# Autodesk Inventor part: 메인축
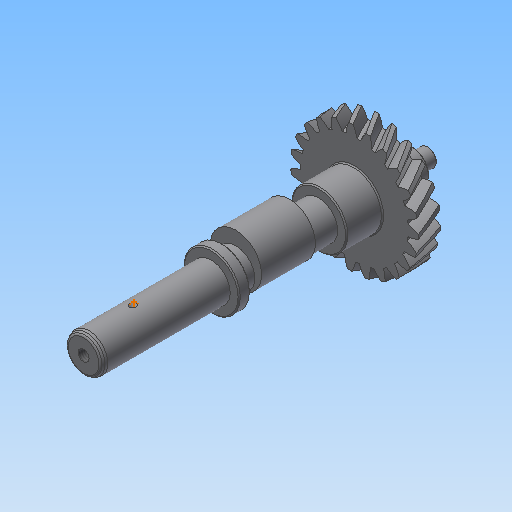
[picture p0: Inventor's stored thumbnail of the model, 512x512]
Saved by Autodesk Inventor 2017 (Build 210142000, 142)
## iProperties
Created: 2016-12
Part Number: 메인축
Material: 강철, 탄소
Document SubType Name: Modeling
Designer: mduedu
Categories: <?xml version="1.0" encoding="UTF-16"?> <MemberInstance><Categories><FamilyTemplate><FamilyTemplateParameter ValueType="xs:double" Id="1" ObjectReferenceKey="da
Density: 7.87 g/cm^3
Appearance: 기본값
Mass: 488.962 g
Surface Area: 171.638 cm^2
Volume: 62.1298 cm^3
CustomPartVersion: 1
Author: mduedu
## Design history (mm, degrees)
sketch "Sketch1"
  geometry: C1 r 28.558 at (0, 0)
  constraints: 1 centre point
  dimensions: "d0" = 57.11622 diameter of C1 (= da_da)
extrude "Extrusion1" new body sketch "Sketch1" distance "d1" = 10 (= da_b); taper "d2" = 0 deg
workplane "Work Plane2"
sketch "Sketch2"
  geometry: C1 r 28.558 at (0, 0) reference; C2 r 26.558 at (0, 0)
  constraints: 1 centre point, 1 coincident
  dimensions: "d3" = 53.11622 diameter of C2 (= da_dw)
feature "피치 지름" sketch "Sketch2" dims "d4" = 10, "d5" = 0
workplane "Work Plane8"
workplane "Work Plane9"
feature "스퍼 기어" dims "da_b" = 10, "da_d" = 53.11622, "da_aw" = 43.87862, "da_da" = 57.11622, "da_df" = 48.11622, "da_dw" = 53.11622, angle "da_beta" = 30 deg, "da_lefttooth" = 10, "da_righttooth" = 0
sketch "스케치3"
  geometry: C1 r 12.5 at (0, 0); 1 further point
  constraints: 1 centre point, 1 coincident
  dimensions: "d49" = 25 diameter of C1
extrude "돌출2" join sketch "스케치3" distance "d50" = 16; taper "d51" = 0 deg
sketch "스케치4"
  geometry: C1 r 8.5 at (0, 0); 1 further point
  constraints: 1 centre point, 1 coincident
  dimensions: "d52" = 17 diameter of C1
extrude "돌출3" join sketch "스케치4" distance "d53" = 105; taper "d54" = 0 deg
sketch "스케치5"
  geometry: C1 r 7.5 at (0, 0); 1 further point
  constraints: 1 centre point, 1 coincident
  dimensions: "d55" = 15 diameter of C1
extrude "돌출4" join sketch "스케치5" distance "d56" = 16; taper "d57" = 0 deg
sketch "스케치6"
  geometry: C1 r 4 at (0, 0); 1 further point
  constraints: 1 centre point, 1 coincident
  dimensions: "d58" = 8 diameter of C1
extrude "돌출5" join sketch "스케치6" distance "d59" = 7; taper "d60" = 0 deg
chamfer "모따기1" distance "d61" = 0.5; stored, may be unused: second distance "d62" = 2, angle "d63" = 45 deg
fillet "모깎기1" dims "d64" = 0.5
node "작업 평면11"
sketch "스케치7"
  geometry: C1 r 11.5 at (0, 3); C2 r 8.5 at (0, 0) reference; 1 further point
  constraints: 1 centre point, 1 tangent, 1 vertical alignment
  dimensions: "d66" = 3 distance of point (0, 0) C1.centre; "d67" = 23 diameter of C1 (derived)
extrude "돌출6" join sketch "스케치7" stored distance "d68" = 24; taper "d69" = 0 deg
node "작업 평면12"
sketch "스케치8"
  geometry: C1 r 12.5 at (0, 0) reference; 1 further point
extrude "돌출7" join sketch "스케치8" distance "d71" = 5; taper "d72" = 0 deg
chamfer "모따기2" distance "d73" = 0.5; stored, may be unused: second distance "d74" = 2, angle "d75" = 45 deg
node "작업 평면13"
sketch "스케치9" dims "d81" = 18
  geometry: L1 (2.5, 95.5)-(-2.5, 95.5); L2 (-2.5, 95.5)-(-2.5, 82.5); L3 (-2.5, 82.5)-(2.5, 82.5); L4 (2.5, 82.5)-(2.5, 95.5); L5 (8.5, 105)-(-8.5, 105) reference; 3 further points
  constraints: 8 end point, 2 horizontal alignment, 2 midpoint, 2 parallel, 1 horizontal, 1 perpendicular, 1 vertical alignment, 4 other
  dimensions: "d79" = 5 distance between parallel lines of L2 L4; "d98" = 7 dimension on L5
extrude "돌출8" cut sketch "스케치9" distance "d83" = 3; taper "d84" = 0 deg
sketch "스케치10"
  geometry: L1 (-8.5, 74)-(-8.5, 131) reference; L2 (8.5, 74)-(8.5, 131) reference; L3 (8.5, 109)-(-8.5, 109); L4 (8.5, 109)-(7, 109); L5 (7, 109)-(8.5, 107.5); L6 (8.5, 107.5)-(8.5, 109); L7 (8.5, 131)-(-8.5, 131) reference; 1 further point
  constraints: 8 end point, 4 point on line, 2 perpendicular
  dimensions: "d86" = 45 deg angle of L5 L4; "d87" = 3 diameter of L5.end L3; "d99" = 22 distance between parallel lines of L7 L3
revolve "회전1" stored, may be unused: angle "d88" = 90 deg
sketch "스케치11"
  geometry: L1 (-8.5, 74)-(-8.5, 131) reference; L2 (-40.7, 131)-(40.7, 131) reference; L3 (-7.45, 131)-(-8.5, 129.181); L4 (0, 131)-(0, 0); L5 (-8.5, 129.181)-(-8.5, 131); L6 (-7.45, 131)-(-8.5, 131)
  constraints: 8 end point, 2 perpendicular, 2 point on line, 1 collinear, 1 midpoint
  dimensions: "d100" = 30 deg angle of L1 L3; "d101" = 14.9 diameter of L3.start L4
revolve "회전2" sketch "스케치11" stored, may be unused: angle "d102" = 90 deg
fillet "모깎기2" dims "d103" = 2, "d113" = 1
hole "구멍2" diameter "d106" = 4.917; stored, may be unused: countersink angle "d110" = 90 deg, drill point angle "d112" = 118 deg; dims "d104" = 10, "d105" = 10, "d107" = 10, "d108" = 4, "d109" = 2, "d111" = 12
node "작업점1"
body "Solid1"
body "Srf1"
node "참조1"
other parameters: "d16" = 43.87862 (= da_aw), "d17" = 0, "d34" = 1.36591 (computed from da_z), "d39" = 0, "d41" = 0, "d43" = 43.87862 (= da_aw), "d46" = 43.87862 (= da_aw), "d47" = 0, "d48" = 0, "d65" = 25, "d70" = 48
